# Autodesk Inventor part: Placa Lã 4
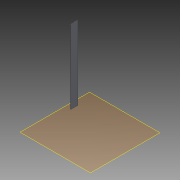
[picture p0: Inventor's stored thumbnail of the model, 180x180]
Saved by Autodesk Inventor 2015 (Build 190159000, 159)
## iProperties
Created: 2015-04
Part Number: Placa Lã 4
Material: Generic
Document SubType Name: Modeling
Designer: suporte
Density: 1 g/cm^3
Appearance: Default
Author: suporte
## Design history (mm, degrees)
workplane "Work Plane1"
sketch "Sketch1"
  geometry: L1 (-825.6, 494.4)-(-874.4, 494.4) reference; L2 (-874.4, 295.6)-(-825.6, 295.6) reference; L3 (-843.75, 295.6)-(-856.25, 295.6); L4 (-856.25, 295.6)-(-856.25, 494.4); L5 (-856.25, 494.4)-(-843.75, 494.4); L6 (-843.75, 494.4)-(-843.75, 295.6); 3 further points
  constraints: 8 end point, 2 midpoint, 2 parallel, 2 point on line, 1 coincident, 1 horizontal, 1 perpendicular
  dimensions: "d0" = 12.5 distance between parallel lines of L4 L6
extrude "Extrusion1" new body sketch "Sketch1" distance "d1" = 2100; taper "d2" = 0 deg
body "Solid1"
node "Reference1"
node "Reference2"
